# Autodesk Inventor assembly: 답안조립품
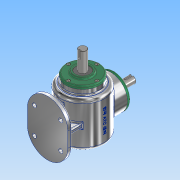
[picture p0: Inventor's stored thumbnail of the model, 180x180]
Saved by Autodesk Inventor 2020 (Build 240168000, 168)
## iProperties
Created: 2023-01
Part Number: 답안조립품
Document SubType Name: Assembly
Designer: user
Author: user
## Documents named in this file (14)
- C:\Users\user\Desktop\730106V1029\답안조립품.iam
- C:\Users\user\Desktop\730106V1029\본체.ipt
- C:\Users\user\Desktop\730106V1029\오일실 17 32 8.ipt
- C:\Users\user\Desktop\730106V1029\커버.ipt
- C:\Users\user\Desktop\730106V1029\서브 축.ipt
- 서브 축.ipt
- C:\Users\user\Desktop\730106V1029\서브 베벨기어.ipt
- C:\Users\user\Desktop\730106V1029\메인 축.ipt
- 메인 축.ipt
- C:\Users\user\Desktop\730106V1029\메인 베벨기어.ipt
- C:\Users\user\Desktop\730106V1029\베어링 6203.ipt
- C:\Users\user\Desktop\730106V1029\M4.ipt
- C:\Users\user\Desktop\730106V1029\키 5x5.ipt
- C:\Users\user\Desktop\730106V1029\키 4x4.ipt
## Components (8 placed, 1 different names)
1. M4:1
2. M4:2
3. M4:3
4. M4:4
5. M4:5
6. M4:6
7. M4:7
8. M4:8
